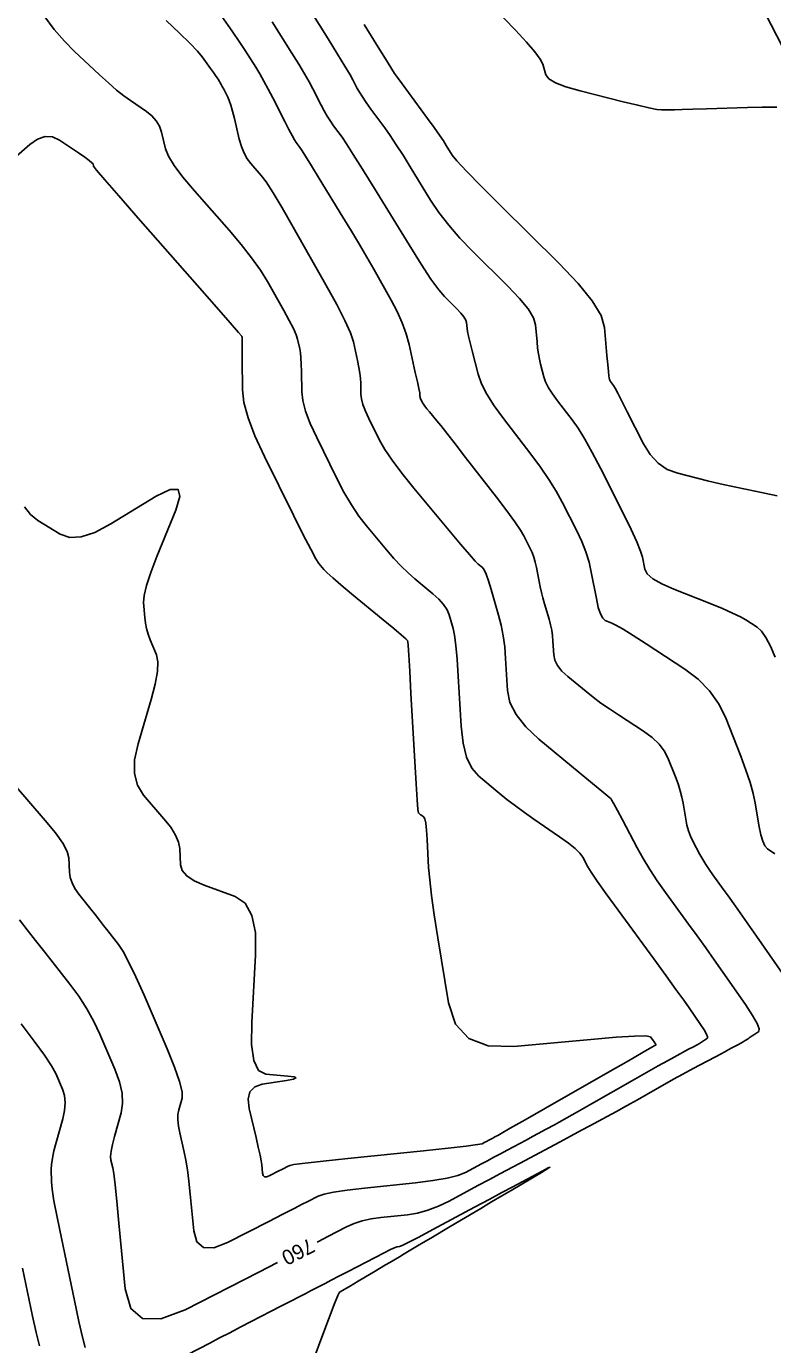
# Model space of a CAD drawing. Extents: x 2082232 to 2083549, y 592624 to 593832.
# Drawn here: x 2082682.7 to 2082717.7, y 593501.1 to 593563 of the extents above; entities that cross this region are included whole.
import ezdxf

# ---------------------------------------------------------------- set-up
doc = ezdxf.new("R2010")
doc.units = 0
for name, color, linetype in [('DT_X_Contour_Major', 7, 'Continuous'), ('DT_X_Contour_Minor', 7, 'Continuous'), ('GE_X_CL_5', 7, 'Continuous')]:
    doc.layers.add(name, color=color, linetype=linetype)

msp = doc.modelspace()

# ---------------------------------------------------------------- linework, layer by layer
at = {"layer": 'DT_X_Contour_Major'}
for points in [[(2082704.096, 593564.43), (2082705.666, 593562.792), (2082706.188, 593562.231), (2082706.575, 593561.778), (2082706.829, 593561.431), (2082706.948, 593561.191), (2082707.087, 593560.695), (2082707.227, 593560.509), (2082707.544, 593560.321), (2082708.036, 593560.131), (2082708.705, 593559.941), (2082710.723, 593559.43), (2082711.403, 593559.263), (2082711.931, 593559.144), (2082712.305, 593559.073), (2082712.527, 593559.05), (2082712.916, 593559.054), (2082713.133, 593559.057), (2082713.492, 593559.066), (2082713.995, 593559.08), (2082714.64, 593559.098), (2082716.55, 593559.154), (2082717.252, 593559.169), (2082717.928, 593559.171)], [(2082703.922, 593537.738), (2082703.782, 593537.883), (2082703.506, 593538.197), (2082703.094, 593538.682), (2082702.545, 593539.337), (2082700.901, 593541.31), (2082700.338, 593542.005), (2082699.882, 593542.61), (2082699.533, 593543.125), (2082699.292, 593543.55), (2082698.791, 593544.564), (2082698.626, 593544.921), (2082698.508, 593545.232), (2082698.436, 593545.496), (2082698.411, 593545.714), (2082698.406, 593546.234), (2082698.396, 593546.446), (2082698.367, 593546.692), (2082698.321, 593546.971), (2082698.256, 593547.285), (2082698.061, 593548.167), (2082697.926, 593548.583), (2082697.665, 593549.168), (2082697.28, 593549.923), (2082696.77, 593550.848), (2082695.243, 593553.541), (2082694.719, 593554.451), (2082694.292, 593555.16), (2082693.964, 593555.668), (2082693.733, 593555.976), (2082693.247, 593556.528), (2082693.077, 593556.755), (2082692.93, 593557.022), (2082692.808, 593557.328), (2082692.709, 593557.673), (2082692.477, 593558.648), (2082692.392, 593558.985), (2082692.311, 593559.264), (2082692.235, 593559.487), (2082692.163, 593559.653), (2082691.976, 593560.019), (2082691.911, 593560.144), (2082691.858, 593560.246), (2082691.815, 593560.323), (2082691.783, 593560.377), (2082691.713, 593560.489), (2082691.672, 593560.551), (2082691.599, 593560.655), (2082691.495, 593560.801), (2082691.36, 593560.987), (2082690.958, 593561.541), (2082690.74, 593561.803), (2082690.388, 593562.173), (2082689.901, 593562.651), (2082689.28, 593563.238)], [(2082696.366, 593505.939), (2082696.419, 593505.966), (2082696.868, 593506.198), (2082697.745, 593506.652), (2082698.091, 593506.808), (2082698.473, 593506.933), (2082698.891, 593507.027), (2082699.344, 593507.091), (2082700.6, 593507.222), (2082701.075, 593507.299), (2082701.56, 593507.431), (2082702.053, 593507.619), (2082702.555, 593507.862), (2082703.907, 593508.585), (2082704.425, 593508.862), (2082704.968, 593509.152), (2082706.123, 593509.77), (2082707.727, 593510.628), (2082708.286, 593510.927), (2082708.762, 593511.181), (2082709.153, 593511.391), (2082710.167, 593511.933), (2082710.442, 593512.082), (2082710.738, 593512.244), (2082711.053, 593512.421), (2082711.389, 593512.612), (2082712.313, 593513.141), (2082712.679, 593513.347), (2082713.084, 593513.572), (2082713.527, 593513.813), (2082714.01, 593514.073), (2082715.35, 593514.788), (2082715.796, 593515.026), (2082716.128, 593515.206), (2082716.347, 593515.327), (2082716.451, 593515.389), (2082716.58, 593515.476), (2082716.633, 593515.512), (2082716.768, 593515.604), (2082716.85, 593515.659), (2082717.081, 593515.816), (2082717.107, 593515.939), (2082717.012, 593516.19), (2082716.795, 593516.57), (2082716.457, 593517.079), (2082715.394, 593518.606), (2082714.995, 593519.176), (2082714.594, 593519.742), (2082714.192, 593520.302), (2082713.789, 593520.857), (2082712.712, 593522.331), (2082712.325, 593522.876), (2082711.975, 593523.407), (2082711.661, 593523.923), (2082711.382, 593524.425), (2082710.686, 593525.743), (2082710.456, 593526.176), (2082710.288, 593526.489), (2082710.181, 593526.68), (2082710.136, 593526.751), (2082710.098, 593526.777), (2082709.997, 593526.859), (2082709.723, 593527.084), (2082709.276, 593527.452), (2082708.656, 593527.965), (2082706.772, 593529.522), (2082706.149, 593530.103), (2082705.695, 593530.678), (2082705.41, 593531.248), (2082705.294, 593531.813), (2082705.207, 593533.311), (2082705.162, 593533.859), (2082705.092, 593534.381), (2082704.997, 593534.875), (2082704.877, 593535.343), (2082704.523, 593536.554), (2082704.398, 593536.959), (2082704.288, 593537.265), (2082704.194, 593537.472), (2082704.114, 593537.581), (2082703.922, 593537.738)], [(2082682.397, 593521.047), (2082682.759, 593520.588), (2082683.152, 593520.087), (2082683.577, 593519.544), (2082684.755, 593518.037), (2082685.174, 593517.466), (2082685.549, 593516.883), (2082685.88, 593516.288), (2082686.166, 593515.682), (2082686.871, 593514.049), (2082687.087, 593513.461), (2082687.208, 593512.923), (2082687.234, 593512.435), (2082687.165, 593511.996), (2082686.853, 593510.892), (2082686.754, 593510.512), (2082686.694, 593510.201), (2082686.67, 593509.958), (2082686.684, 593509.784), (2082686.772, 593509.412), (2082686.815, 593509.146), (2082686.877, 593508.626), (2082686.959, 593507.852), (2082687.06, 593506.825), (2082687.355, 593503.747), (2082687.614, 593502.82), (2082688.169, 593502.347), (2082689.02, 593502.328), (2082690.167, 593502.764), (2082693.62, 593504.531), (2082694.497, 593504.98)]]:
    msp.add_lwpolyline(points, dxfattribs=at)
at = {"layer": 'DT_X_Contour_Minor'}
for points in [[(2082695.527, 593564.533), (2082696.871, 593562.383), (2082697.321, 593561.658), (2082697.666, 593561.097), (2082697.904, 593560.698), (2082698.036, 593560.463), (2082698.245, 593560.052), (2082698.344, 593559.876), (2082698.484, 593559.656), (2082698.665, 593559.392), (2082698.887, 593559.084), (2082699.534, 593558.203), (2082699.791, 593557.841), (2082700.076, 593557.415), (2082700.391, 593556.927), (2082700.734, 593556.375), (2082701.688, 593554.82), (2082702.079, 593554.233), (2082702.536, 593553.638), (2082703.06, 593553.035), (2082703.65, 593552.424), (2082705.314, 593550.784), (2082705.863, 593550.208), (2082706.262, 593549.712), (2082706.512, 593549.295), (2082706.612, 593548.958), (2082706.68, 593548.162), (2082706.709, 593547.874), (2082706.747, 593547.603), (2082706.792, 593547.352), (2082706.846, 593547.119), (2082707.002, 593546.522), (2082707.085, 593546.284), (2082707.219, 593546.018), (2082707.403, 593545.725), (2082707.638, 593545.403), (2082708.33, 593544.508), (2082708.608, 593544.115), (2082708.922, 593543.604), (2082709.272, 593542.978), (2082709.659, 593542.235), (2082710.737, 593540.098), (2082711.095, 593539.37), (2082711.363, 593538.789), (2082711.54, 593538.355), (2082711.627, 593538.067), (2082711.735, 593537.497), (2082711.851, 593537.278), (2082712.116, 593537.049), (2082712.53, 593536.811), (2082713.095, 593536.563), (2082714.799, 593535.889), (2082715.383, 593535.652), (2082715.857, 593535.445), (2082716.221, 593535.269), (2082716.475, 593535.124), (2082717.006, 593534.779), (2082717.208, 593534.594), (2082717.418, 593534.297), (2082717.634, 593533.888), (2082717.858, 593533.369)], [(2082700.948, 593537.046), (2082700.628, 593537.326), (2082700.298, 593537.647), (2082699.96, 593538.008), (2082699.613, 593538.41), (2082698.674, 593539.536), (2082698.322, 593539.994), (2082697.971, 593540.523), (2082697.621, 593541.123), (2082697.272, 593541.794), (2082696.341, 593543.679), (2082696.035, 593544.343), (2082695.815, 593544.92), (2082695.682, 593545.412), (2082695.636, 593545.817), (2082695.626, 593546.783), (2082695.619, 593547.121), (2082695.603, 593547.41), (2082695.578, 593547.65), (2082695.546, 593547.841), (2082695.447, 593548.286), (2082695.379, 593548.496), (2082695.247, 593548.791), (2082695.053, 593549.172), (2082694.796, 593549.638), (2082694.025, 593550.997), (2082693.696, 593551.529), (2082693.287, 593552.108), (2082692.798, 593552.732), (2082692.229, 593553.402), (2082690.603, 593555.251), (2082690.061, 593555.895), (2082689.654, 593556.438), (2082689.382, 593556.881), (2082689.245, 593557.224), (2082689.059, 593558.006), (2082688.962, 593558.286), (2082688.812, 593558.541), (2082688.609, 593558.771), (2082688.353, 593558.975), (2082687.597, 593559.485), (2082687.294, 593559.704), (2082686.95, 593559.98), (2082686.565, 593560.311), (2082686.141, 593560.698), (2082684.954, 593561.804), (2082684.499, 593562.267), (2082684.024, 593562.824), (2082683.529, 593563.477)], [(2082691.881, 593563.434), (2082692.371, 593562.744), (2082692.738, 593562.212), (2082692.985, 593561.837), (2082693.479, 593561.046), (2082693.668, 593560.734), (2082693.864, 593560.392), (2082694.067, 593560.02), (2082694.277, 593559.617), (2082694.845, 593558.503), (2082695.039, 593558.129), (2082695.192, 593557.84), (2082695.306, 593557.637), (2082695.38, 593557.521), (2082695.524, 593557.324), (2082695.624, 593557.175), (2082695.813, 593556.876), (2082696.093, 593556.425), (2082696.462, 593555.824), (2082697.569, 593554.019), (2082697.971, 593553.359), (2082698.346, 593552.732), (2082698.694, 593552.138), (2082699.016, 593551.577), (2082699.839, 593550.126), (2082700.123, 593549.588), (2082700.357, 593549.062), (2082700.541, 593548.549), (2082700.675, 593548.048), (2082700.967, 593546.729), (2082701.063, 593546.293), (2082701.131, 593545.974), (2082701.173, 593545.771), (2082701.186, 593545.685), (2082701.187, 593545.612), (2082701.191, 593545.581), (2082701.201, 593545.543), (2082701.217, 593545.5), (2082701.241, 593545.449), (2082701.311, 593545.306), (2082701.351, 593545.239), (2082701.417, 593545.147), (2082701.509, 593545.028), (2082701.627, 593544.883), (2082701.978, 593544.463), (2082702.161, 593544.237), (2082702.446, 593543.876), (2082702.834, 593543.379), (2082703.325, 593542.747), (2082704.771, 593540.88), (2082705.259, 593540.241), (2082705.637, 593539.725), (2082705.906, 593539.332), (2082706.066, 593539.061), (2082706.347, 593538.505), (2082706.445, 593538.291), (2082706.529, 593538.067), (2082706.598, 593537.833), (2082706.653, 593537.589), (2082706.779, 593536.925), (2082706.83, 593536.673), (2082706.89, 593536.416), (2082706.957, 593536.153), (2082707.032, 593535.885), (2082707.243, 593535.164), (2082707.313, 593534.896), (2082707.368, 593534.635), (2082707.407, 593534.381), (2082707.429, 593534.133), (2082707.466, 593533.481), (2082707.519, 593533.234), (2082707.647, 593532.982), (2082707.851, 593532.726), (2082708.132, 593532.465), (2082708.981, 593531.763), (2082709.315, 593531.497), (2082709.679, 593531.225), (2082710.074, 593530.947), (2082710.5, 593530.663), (2082711.676, 593529.897), (2082712.078, 593529.604), (2082712.404, 593529.299), (2082712.652, 593528.981), (2082712.823, 593528.651), (2082713.176, 593527.755), (2082713.298, 593527.426), (2082713.398, 593527.11), (2082713.477, 593526.808), (2082713.535, 593526.52), (2082713.66, 593525.769), (2082713.716, 593525.493), (2082713.792, 593525.23), (2082713.886, 593524.98), (2082713.998, 593524.742), (2082714.324, 593524.124), (2082714.454, 593523.89), (2082714.599, 593523.652), (2082714.759, 593523.409), (2082714.933, 593523.162), (2082715.419, 593522.498), (2082715.653, 593522.173), (2082715.989, 593521.697), (2082716.429, 593521.07), (2082716.972, 593520.291), (2082718.557, 593518.013)], [(2082694.256, 593563.185), (2082695.175, 593561.714), (2082695.495, 593561.196), (2082695.765, 593560.744), (2082695.985, 593560.359), (2082696.156, 593560.04), (2082696.545, 593559.278), (2082696.692, 593559.003), (2082696.838, 593558.748), (2082696.986, 593558.515), (2082697.134, 593558.302), (2082697.529, 593557.764), (2082697.735, 593557.462), (2082698.057, 593556.962), (2082698.494, 593556.264), (2082699.047, 593555.367), (2082700.676, 593552.711), (2082701.238, 593551.813), (2082701.702, 593551.109), (2082702.067, 593550.601), (2082702.335, 593550.288), (2082702.919, 593549.713), (2082703.111, 593549.511), (2082703.251, 593549.337), (2082703.339, 593549.19), (2082703.374, 593549.072), (2082703.398, 593548.793), (2082703.419, 593548.65), (2082703.465, 593548.428), (2082703.536, 593548.129), (2082703.631, 593547.753), (2082703.919, 593546.644), (2082704.074, 593546.203), (2082704.323, 593545.709), (2082704.665, 593545.164), (2082705.101, 593544.567), (2082706.388, 593542.905), (2082706.842, 593542.296), (2082707.239, 593541.717), (2082707.579, 593541.168), (2082707.862, 593540.648), (2082708.542, 593539.301), (2082708.776, 593538.801), (2082708.968, 593538.311), (2082709.119, 593537.832), (2082709.228, 593537.362), (2082709.464, 593536.124), (2082709.556, 593535.712), (2082709.655, 593535.404), (2082709.763, 593535.201), (2082709.878, 593535.101), (2082710.195, 593534.976), (2082710.384, 593534.879), (2082710.715, 593534.683), (2082711.186, 593534.388), (2082711.797, 593533.994), (2082713.617, 593532.81), (2082714.247, 593532.336), (2082714.775, 593531.802), (2082715.199, 593531.208), (2082715.52, 593530.555), (2082716.238, 593528.732), (2082716.483, 593528.082), (2082716.677, 593527.498), (2082716.822, 593526.98), (2082716.917, 593526.528), (2082717.103, 593525.411), (2082717.18, 593525.033), (2082717.271, 593524.737), (2082717.377, 593524.523), (2082717.498, 593524.391), (2082717.839, 593524.148)], [(2082698.567, 593563.052), (2082699.148, 593562.12), (2082699.567, 593561.449), (2082699.823, 593561.037), (2082699.915, 593560.885), (2082699.945, 593560.827), (2082699.997, 593560.75), (2082700.13, 593560.565), (2082700.345, 593560.27), (2082700.641, 593559.865), (2082701.539, 593558.642), (2082701.846, 593558.219), (2082702.096, 593557.868), (2082702.287, 593557.59), (2082702.421, 593557.384), (2082702.699, 593556.929), (2082702.919, 593556.654), (2082703.37, 593556.167), (2082704.053, 593555.469), (2082704.966, 593554.56), (2082707.709, 593551.855), (2082708.615, 593550.906), (2082709.273, 593550.088), (2082709.685, 593549.4), (2082709.85, 593548.843), (2082709.961, 593547.532), (2082709.999, 593547.098), (2082710.028, 593546.778), (2082710.049, 593546.574), (2082710.062, 593546.485), (2082710.084, 593546.399), (2082710.096, 593546.365), (2082710.115, 593546.328), (2082710.141, 593546.286), (2082710.174, 593546.24), (2082710.273, 593546.112), (2082710.341, 593546), (2082710.471, 593545.759), (2082710.662, 593545.389), (2082710.916, 593544.89), (2082711.673, 593543.389), (2082711.987, 593542.88), (2082712.36, 593542.479), (2082712.792, 593542.186), (2082713.283, 593542.002), (2082714.673, 593541.653), (2082715.269, 593541.511), (2082716.015, 593541.345), (2082716.91, 593541.156), (2082717.955, 593540.944)], [(2082681.881, 593556.542), (2082682.871, 593557.422), (2082683.237, 593557.683), (2082683.594, 593557.805), (2082683.94, 593557.789), (2082684.277, 593557.634), (2082685.162, 593557.036), (2082685.453, 593556.835), (2082685.664, 593556.68), (2082685.794, 593556.572), (2082685.843, 593556.511), (2082685.868, 593556.41), (2082686.005, 593556.229), (2082686.4, 593555.763), (2082687.051, 593555.011), (2082687.959, 593553.975), (2082690.724, 593550.829), (2082691.632, 593549.796), (2082692.282, 593549.056), (2082692.674, 593548.608), (2082692.808, 593548.452), (2082692.822, 593548.428), (2082692.826, 593548.42), (2082692.83, 593548.414), (2082692.832, 593548.408), (2082692.833, 593548.405), (2082692.835, 593548.397), (2082692.836, 593548.328), (2082692.838, 593548.128), (2082692.842, 593547.796), (2082692.846, 593547.332), (2082692.86, 593545.92), (2082692.928, 593545.327), (2082693.122, 593544.609), (2082693.443, 593543.764), (2082693.891, 593542.794), (2082695.252, 593540.038), (2082695.709, 593539.121), (2082696.061, 593538.436), (2082696.307, 593537.983), (2082696.447, 593537.762), (2082696.68, 593537.483), (2082696.826, 593537.334), (2082697.091, 593537.096), (2082697.473, 593536.769), (2082697.973, 593536.353), (2082699.465, 593535.124), (2082699.955, 593534.719), (2082700.307, 593534.423), (2082700.521, 593534.237), (2082700.596, 593534.16), (2082700.613, 593534.102), (2082700.627, 593533.934), (2082700.657, 593533.472), (2082700.703, 593532.716), (2082700.764, 593531.667), (2082700.948, 593528.477), (2082701.01, 593527.43), (2082701.057, 593526.678), (2082701.091, 593526.224), (2082701.11, 593526.065), (2082701.141, 593526.039), (2082701.157, 593526.027), (2082701.182, 593526.009), (2082701.214, 593525.986), (2082701.254, 593525.958), (2082701.373, 593525.877), (2082701.415, 593525.788), (2082701.454, 593525.583), (2082701.488, 593525.262), (2082701.518, 593524.825), (2082701.594, 593523.504), (2082701.642, 593522.927), (2082701.729, 593522.187), (2082701.856, 593521.283), (2082702.023, 593520.216), (2082702.52, 593517.154), (2082702.851, 593516.165), (2082703.475, 593515.494), (2082704.389, 593515.142), (2082705.595, 593515.109), (2082709.199, 593515.445), (2082710.388, 593515.547), (2082711.251, 593515.601), (2082711.788, 593515.607), (2082711.999, 593515.565), (2082712.128, 593515.388), (2082712.172, 593515.329), (2082712.204, 593515.284), (2082712.227, 593515.253), (2082712.239, 593515.237), (2082712.257, 593515.211), (2082712.262, 593515.202), (2082712.266, 593515.196), (2082712.267, 593515.192), (2082712.267, 593515.189), (2082712.263, 593515.187), (2082712.262, 593515.186), (2082712.261, 593515.185), (2082712.259, 593515.184), (2082712.259, 593515.184), (2082712.256, 593515.182), (2082712.255, 593515.181), (2082712.251, 593515.179), (2082712.245, 593515.176), (2082712.238, 593515.172), (2082712.215, 593515.16), (2082712.071, 593515.078), (2082711.654, 593514.84), (2082710.966, 593514.446), (2082710.005, 593513.897), (2082707.081, 593512.224), (2082706.119, 593511.674), (2082705.424, 593511.277), (2082704.996, 593511.033), (2082704.837, 593510.943), (2082704.768, 593510.906), (2082704.739, 593510.89), (2082704.701, 593510.87), (2082704.655, 593510.845), (2082704.6, 593510.816), (2082704.445, 593510.733), (2082704.388, 593510.702), (2082704.333, 593510.673), (2082704.28, 593510.645), (2082704.23, 593510.618), (2082704.099, 593510.548), (2082703.89, 593510.508), (2082703.362, 593510.439), (2082702.514, 593510.343), (2082701.347, 593510.219), (2082697.808, 593509.851), (2082696.642, 593509.728), (2082695.798, 593509.634), (2082695.275, 593509.569), (2082695.074, 593509.533), (2082694.966, 593509.477), (2082694.911, 593509.449), (2082694.826, 593509.405), (2082694.711, 593509.346), (2082694.567, 593509.272), (2082694.142, 593509.055), (2082694.001, 593509.002), (2082693.896, 593509.004), (2082693.828, 593509.062), (2082693.796, 593509.176), (2082693.76, 593509.554), (2082693.733, 593509.742), (2082693.68, 593510.02), (2082693.6, 593510.389), (2082693.494, 593510.849), (2082693.176, 593512.197), (2082693.125, 593512.647), (2082693.209, 593512.988), (2082693.43, 593513.219), (2082693.788, 593513.341), (2082694.922, 593513.519), (2082695.245, 593513.581), (2082695.364, 593513.636), (2082695.279, 593513.682), (2082694.99, 593513.721), (2082693.947, 593513.812), (2082693.613, 593513.99), (2082693.393, 593514.454), (2082693.288, 593515.206), (2082693.297, 593516.244), (2082693.474, 593519.394), (2082693.464, 593520.452), (2082693.301, 593521.264), (2082692.985, 593521.831), (2082692.517, 593522.151), (2082691.063, 593522.678), (2082690.584, 593522.887), (2082690.239, 593523.116), (2082690.027, 593523.368), (2082689.948, 593523.641), (2082689.916, 593524.397), (2082689.861, 593524.697), (2082689.718, 593525.03), (2082689.489, 593525.397), (2082689.172, 593525.796), (2082688.212, 593526.905), (2082687.926, 593527.367), (2082687.787, 593527.921), (2082687.797, 593528.566), (2082687.955, 593529.304), (2082688.574, 593531.392), (2082688.763, 593532.111), (2082688.867, 593532.699), (2082688.886, 593533.158), (2082688.819, 593533.486), (2082688.529, 593534.189), (2082688.431, 593534.452), (2082688.355, 593534.715), (2082688.301, 593534.978), (2082688.269, 593535.241), (2082688.214, 593535.942)], [(2082688.214, 593535.942), (2082688.238, 593536.274), (2082688.35, 593536.744), (2082688.552, 593537.351), (2082688.841, 593538.096), (2082689.732, 593540.267), (2082689.925, 593540.919), (2082689.835, 593541.245), (2082689.463, 593541.246), (2082688.807, 593540.922), (2082686.682, 593539.624), (2082685.936, 593539.228), (2082685.291, 593539.016), (2082684.748, 593538.986), (2082684.306, 593539.139), (2082683.261, 593539.792), (2082682.908, 593540.073), (2082682.631, 593540.425)], [(2082682.152, 593527.384), (2082683.601, 593525.71), (2082684.078, 593525.13), (2082684.422, 593524.643), (2082684.633, 593524.252), (2082684.71, 593523.955), (2082684.738, 593523.288), (2082684.773, 593523.037), (2082684.858, 593522.782), (2082684.993, 593522.523), (2082685.178, 593522.261), (2082685.736, 593521.558), (2082685.943, 593521.297), (2082686.145, 593521.041), (2082686.342, 593520.79), (2082686.535, 593520.544), (2082687.041, 593519.896), (2082687.259, 593519.565), (2082687.53, 593519.058), (2082687.857, 593518.376), (2082688.237, 593517.518), (2082689.326, 593514.996), (2082689.675, 593514.143), (2082689.909, 593513.475), (2082690.025, 593512.991), (2082690.026, 593512.693), (2082689.871, 593512.145), (2082689.83, 593511.923), (2082689.823, 593511.668), (2082689.851, 593511.381), (2082689.914, 593511.06), (2082690.126, 593510.16), (2082690.204, 593509.784), (2082690.277, 593509.331), (2082690.345, 593508.799), (2082690.41, 593508.19), (2082690.576, 593506.462), (2082690.721, 593505.941), (2082691.033, 593505.675), (2082691.51, 593505.665), (2082692.154, 593505.91), (2082694.094, 593506.902), (2082694.753, 593507.24), (2082695.277, 593507.508), (2082695.665, 593507.707), (2082695.917, 593507.838), (2082696.409, 593508.093), (2082696.683, 593508.188), (2082697.135, 593508.283), (2082697.767, 593508.378), (2082698.576, 593508.471), (2082700.973, 593508.721), (2082701.794, 593508.821), (2082702.461, 593508.935), (2082702.971, 593509.063), (2082703.327, 593509.205), (2082704.068, 593509.601), (2082704.353, 593509.754), (2082704.65, 593509.913), (2082704.961, 593510.079), (2082705.284, 593510.252), (2082706.164, 593510.722), (2082706.471, 593510.886), (2082706.731, 593511.026), (2082707.114, 593511.23), (2082707.502, 593511.438), (2082707.719, 593511.557), (2082708.081, 593511.761), (2082708.586, 593512.048), (2082709.235, 593512.418), (2082711.159, 593513.519), (2082711.822, 593513.897), (2082712.369, 593514.206), (2082712.799, 593514.446), (2082713.113, 593514.616), (2082713.794, 593514.98), (2082714.021, 593515.101), (2082714.189, 593515.193), (2082714.301, 593515.254), (2082714.354, 593515.286), (2082714.674, 593515.503), (2082714.687, 593515.565), (2082714.639, 593515.693), (2082714.529, 593515.886), (2082714.357, 593516.145), (2082713.816, 593516.921), (2082713.561, 593517.283), (2082713.199, 593517.786), (2082712.732, 593518.431), (2082712.159, 593519.216), (2082710.49, 593521.5), (2082709.931, 593522.27), (2082709.507, 593522.868), (2082709.217, 593523.293), (2082709.062, 593523.546), (2082708.827, 593523.991), (2082708.693, 593524.176), (2082708.468, 593524.397), (2082708.15, 593524.655), (2082707.741, 593524.949), (2082706.527, 593525.783), (2082706.084, 593526.094), (2082705.665, 593526.4), (2082705.27, 593526.703), (2082704.899, 593527.002), (2082703.941, 593527.793), (2082703.62, 593528.163), (2082703.376, 593528.678), (2082703.21, 593529.339), (2082703.121, 593530.145), (2082702.986, 593532.489), (2082702.933, 593533.288), (2082702.875, 593533.926), (2082702.812, 593534.405), (2082702.745, 593534.723), (2082702.56, 593535.357), (2082702.46, 593535.598), (2082702.298, 593535.844), (2082702.075, 593536.095), (2082701.79, 593536.353), (2082700.948, 593537.046)], [(2082685.473, 593500.991), (2082685.347, 593501.48), (2082685.179, 593502.213), (2082684.97, 593503.19), (2082684.358, 593506.12), (2082684.157, 593507.108), (2082684.012, 593507.877), (2082683.924, 593508.426), (2082683.892, 593508.755), (2082683.882, 593509.339), (2082683.893, 593509.583), (2082683.935, 593509.875), (2082684.007, 593510.217), (2082684.109, 593510.607), (2082684.422, 593511.714), (2082684.509, 593512.112), (2082684.537, 593512.476), (2082684.506, 593512.806), (2082684.415, 593513.102), (2082684.094, 593513.846), (2082683.902, 593514.201), (2082683.567, 593514.708), (2082683.089, 593515.367), (2082682.468, 593516.178)], [(2082695.459, 593498.426), (2082696.536, 593501.35), (2082696.894, 593502.312), (2082697.159, 593503.005), (2082697.332, 593503.429), (2082697.412, 593503.583), (2082697.55, 593503.665), (2082697.629, 593503.712), (2082697.738, 593503.777), (2082697.877, 593503.859), (2082698.288, 593504.103), (2082698.623, 593504.302), (2082698.811, 593504.413), (2082699.012, 593504.532), (2082699.566, 593504.861), (2082699.777, 593504.986), (2082700.219, 593505.248), (2082700.449, 593505.385), (2082701.072, 593505.755), (2082701.344, 593505.916), (2082701.69, 593506.121), (2082702.609, 593506.666), (2082704.035, 593507.512), (2082704.55, 593507.818), (2082705.028, 593508.101), (2082705.468, 593508.362), (2082706.893, 593509.207), (2082707.183, 593509.382), (2082707.285, 593509.45), (2082707.2, 593509.413), (2082706.927, 593509.27), (2082705.537, 593508.527), (2082705.032, 593508.256), (2082704.435, 593507.937), (2082703.745, 593507.568), (2082701.783, 593506.519), (2082701.134, 593506.174), (2082700.659, 593505.927), (2082700.356, 593505.776), (2082700.226, 593505.723), (2082700.112, 593505.711), (2082700.015, 593505.677), (2082699.811, 593505.582), (2082699.499, 593505.427), (2082699.08, 593505.212), (2082697.819, 593504.558), (2082697.383, 593504.332), (2082697.021, 593504.145), (2082696.733, 593503.996), (2082696.518, 593503.886), (2082696.045, 593503.644), (2082695.824, 593503.53), (2082695.519, 593503.373), (2082695.127, 593503.171), (2082694.651, 593502.924), (2082693.266, 593502.207), (2082692.755, 593501.942), (2082692.261, 593501.686), (2082691.784, 593501.439), (2082691.324, 593501.201), (2082689.712, 593500.366)], [(2082683.329, 593501.07), (2082683.169, 593501.692), (2082682.998, 593502.46), (2082682.529, 593504.706)]]:
    msp.add_lwpolyline(points, dxfattribs=at)
at = {"layer": 'GE_X_CL_5'}
msp.add_arc((2082101.49, 593242.014), 694.785, 25.520029, 37.696362, dxfattribs=at)

# ---------------------------------------------------------------- texts
at = {"layer": 'DT_X_Contour_Major'}
msp.add_text('760', height=0.7, rotation=207.15477, dxfattribs=at).set_placement((2082696.008, 593506.148))

doc.saveas('drawing.dxf')
